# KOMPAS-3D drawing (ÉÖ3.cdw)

Referenced files in F:\1я детская\: РЩ3.cdw
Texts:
  Электроснабжение первой детской клинической больницы  по адресу: г. Иваново, ул. Мальцева д.3
  Microsoft
  Текст на чертеже
  Размерные надписи
  Шероховатость
  Линия-выноска #1
  Линия-выноска #2
  Линия-выноска #3
  Отклонения формы и база
  Заголовок таблицы
  Ячейка таблицы
  Стрелка вида
  Обозначение изменения
  Фигурная скобка
  Номер узла
  Марка координационной оси
  VRCB
  Выносная надпись
  Обозначение узла
  Марка/позиционное обозначение с линией-выноской
  Марка/позиционное обозначение на линии
  Марка/позиционное обозначение без линии-выноски
  ВА 47-29 (1)
  ВА 47-29 (3)
  Номер группы
  Р кВт
  Ток, А
  Гр10
  Гр11
  Гр12
  Гр13
  Освещение
  ВВГнгLS 5х10 мм 2  скрыто в ПВХ
  трубе от ВРУ
  ВВГнгLS 3х1,5 cкрыто
  РЩ-3(ЩРВ-24)
  Гр14
  Гр15
  Бактарецидные
  лампы
  Гр15а
  Розетки
  Гр15б
  Гр15в
  АД12М
  CONTINUOUS0
  Электроснабжение первой детской клинической больницы
  по адресу: г. Иваново, ул. Мальцева д.3
  ГИП
  Разработ
  Однолинейная расчётная схема щита
  РЩ-3
  Кочетков
  ООО "Мастер Лайт"
Dimensions and other numbers on the sheet: 2012-0011-ЭС; 7; 10А; 16А; 0.5; 0.12; 0.24; 1.1; 1.0; 5.05; 16А Iсраб=30мА; 4; 1:1; 5; 0; 1; 2; 3; 6; 8; 9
